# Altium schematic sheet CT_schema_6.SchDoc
size 376 x 245 mm
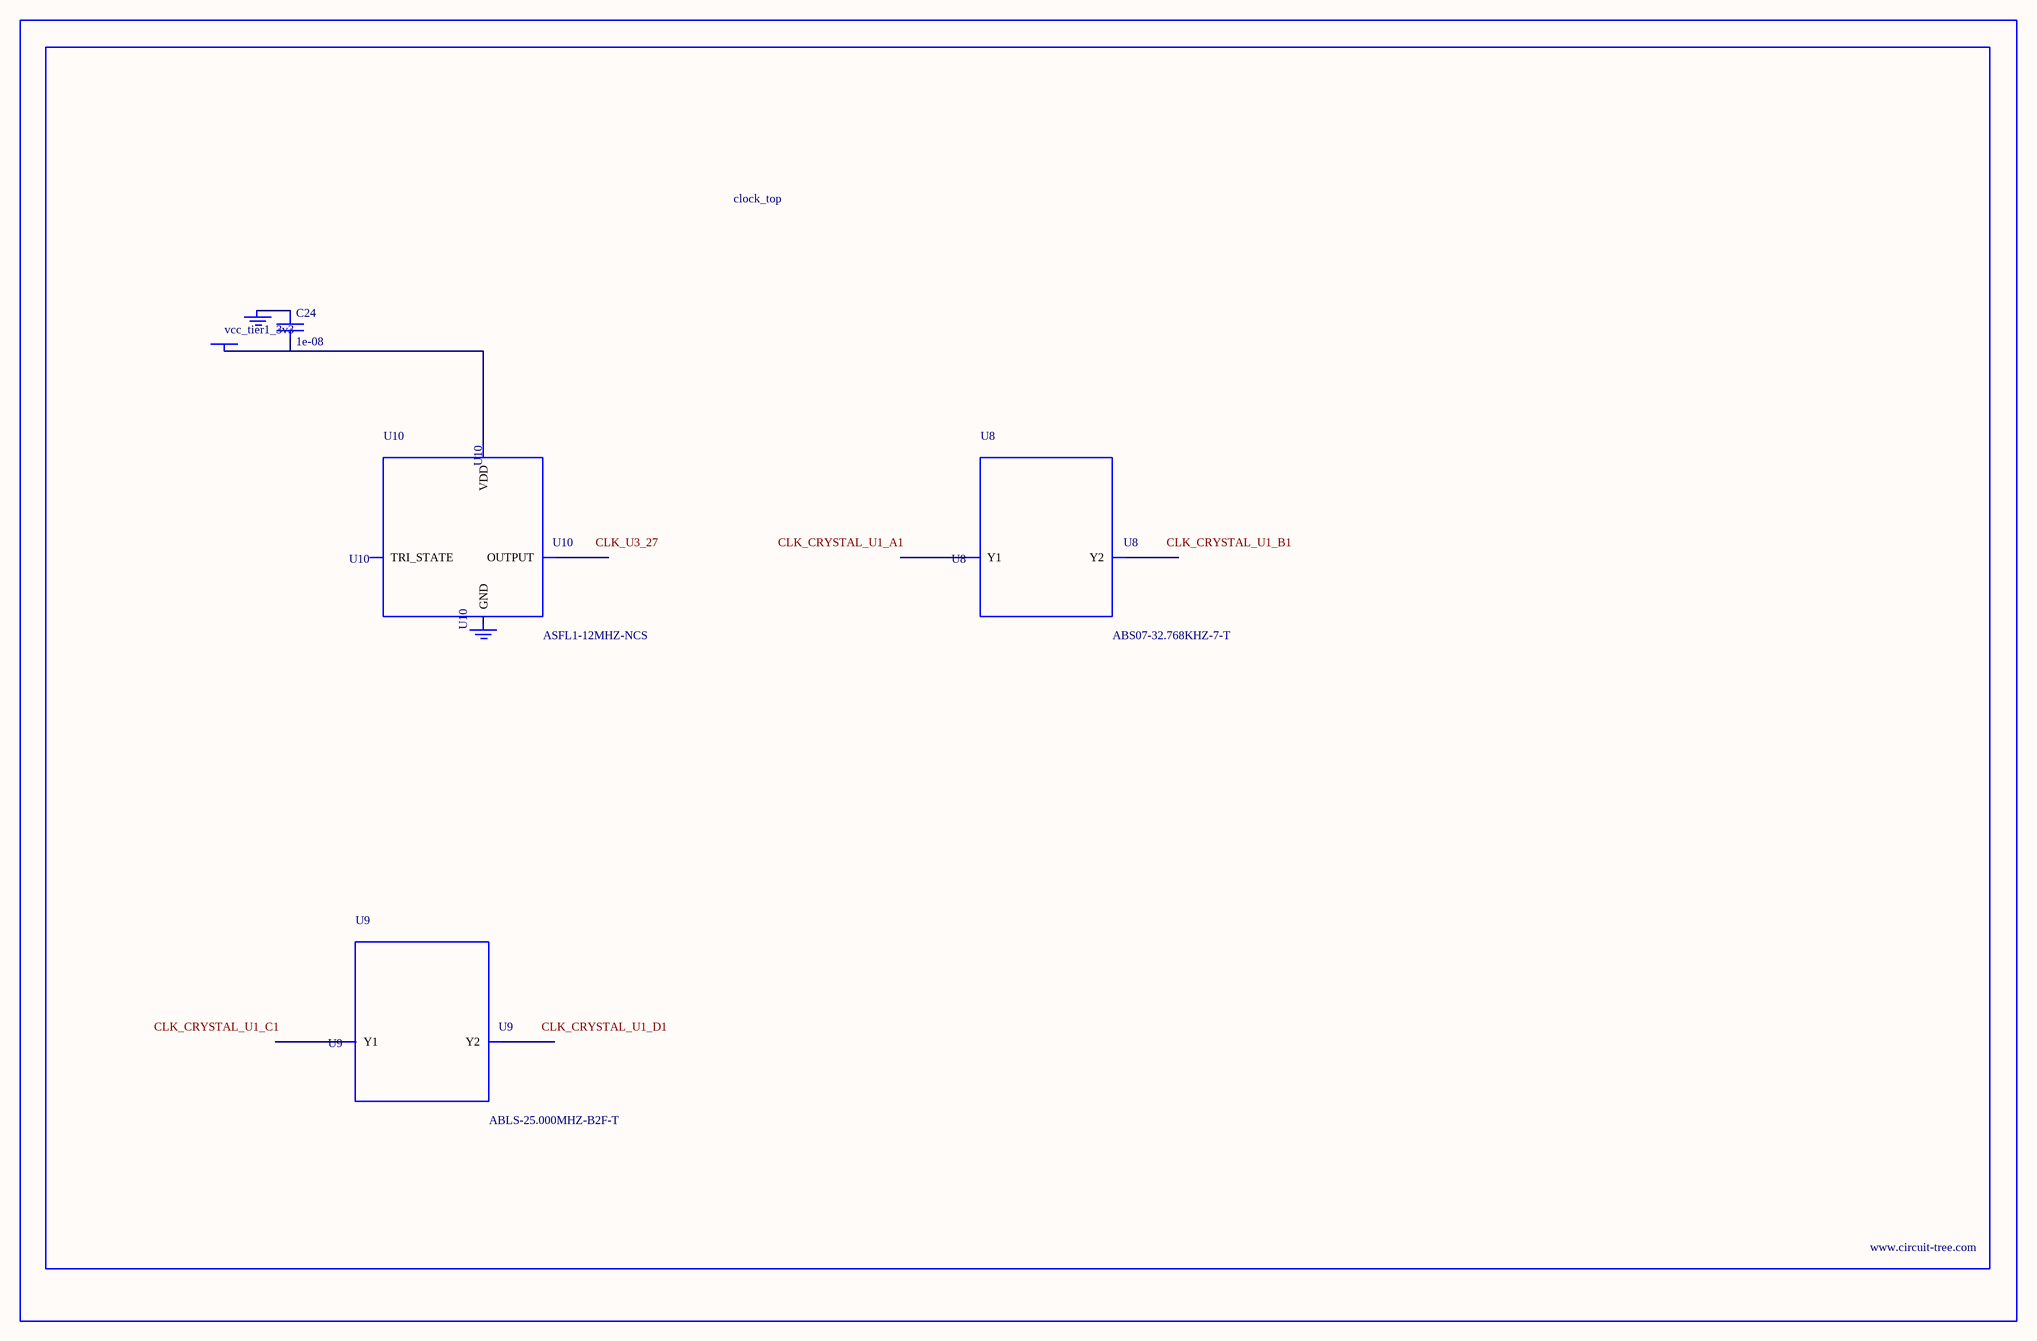
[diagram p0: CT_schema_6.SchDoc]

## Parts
BORDER5  (no value)
C24  1e-08  [C0402]
GND_INSTANCE_5_0  (no value)
GND_INSTANCE_5_1  (no value)
POWER_INSTANCE_5_0  vcc_tier1_3v3
U8  ABS07-32.768KHZ-7-T  [ABS07-32.768KHZ-7-T]
U9  ABLS-25.000MHZ-B2F-T  [ABLS-25.000MHZ-B2F-T]
U10  ASFL1-12MHZ-NCS  [ASFL1]

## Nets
NetC24_1: C24.1 GND_INSTANCE_5_0.0(GND)
NetC24_2: C24.2 POWER_INSTANCE_5_0.0(PWR) U10.4(VDD)

Not connected (* = marked no-connect by the designer): GND_INSTANCE_5_1 0(GND); U8 1(Y1) 2(Y2); U9 1(Y1) 2(Y2); U10 1(TRI_STATE) 2(GND) 3(OUTPUT)

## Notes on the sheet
- Labels drawn without touching a wire or pin: CLK_CRYSTAL_U1_A1, CLK_CRYSTAL_U1_B1, CLK_CRYSTAL_U1_C1, CLK_CRYSTAL_U1_D1, CLK_U3_27

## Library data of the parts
BORDER5 = BORDER_PAGE5
C24 = C0402C103K3RAC
GND_INSTANCE_5_0 GND_INSTANCE_5_1 = GND
POWER_INSTANCE_5_0 = PWR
